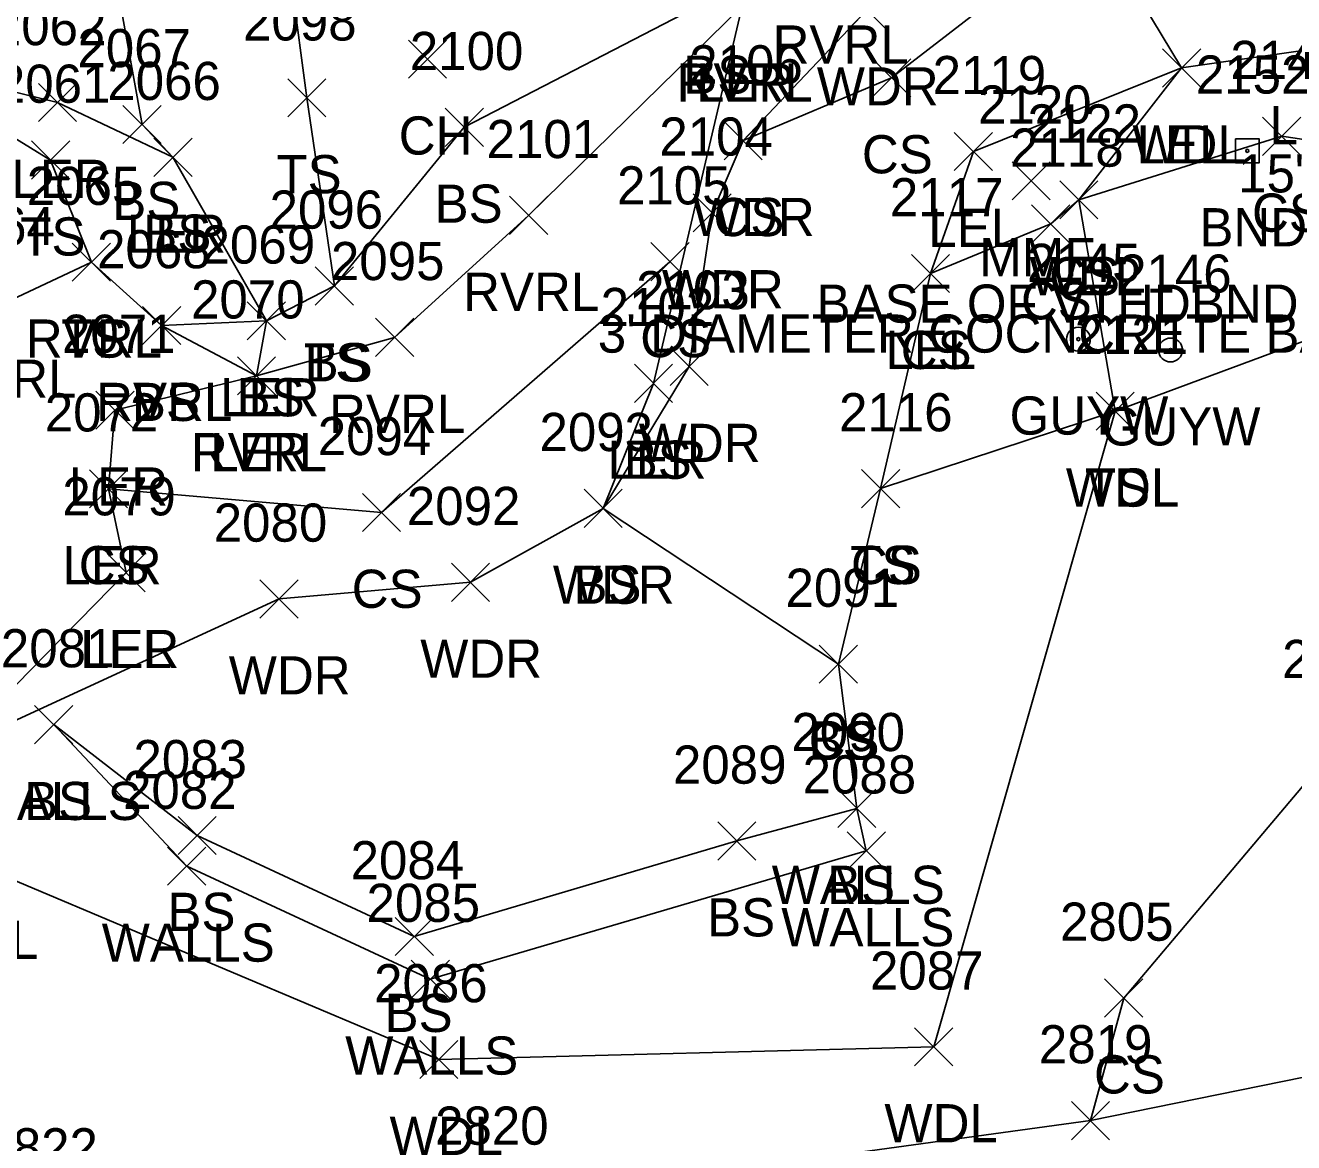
# Model space of a CAD drawing. Extents: x 1504228 to 1506103, y 437717 to 440106.
# Drawn here: x 1505135.1 to 1505201.5, y 438079.5 to 438138 of the extents above; entities that cross this region are included whole.
import ezdxf

# ---------------------------------------------------------------- set-up
doc = ezdxf.new("R2010")
doc.units = 0
for name, color, linetype in [('D_C', 7, 'Continuous'), ('L_A', 7, 'Continuous'), ('L_C', 7, 'Continuous'), ('L_I', 7, 'Continuous'), ('L_TIC', 7, 'Continuous'), ('LARO', 7, 'Continuous'), ('LAWA', 7, 'Continuous'), ('LAWE', 7, 'Continuous'), ('LELB', 7, 'Continuous'), ('LWS', 7, 'Continuous'), ('M_A', 7, 'Continuous'), ('M_C', 7, 'Continuous'), ('M_I', 7, 'Continuous'), ('MHBP', 7, 'Continuous'), ('R_I', 7, 'Continuous'), ('R_TIC', 7, 'Continuous'), ('RDG', 7, 'Continuous'), ('U_A', 7, 'Continuous'), ('U_I', 7, 'Continuous'), ('UPGW', 7, 'Continuous')]:
    doc.layers.add(name, color=color, linetype=linetype)

msp = doc.modelspace()

# ---------------------------------------------------------------- linework, layer by layer
at = {"layer": 'L_TIC'}
for points in [[(1505178.199, 438137.842), (1505180.199, 438139.842)], [(1505180.199, 438137.842), (1505178.199, 438139.842)], [(1505155.163, 438135.267), (1505157.163, 438137.267)], [(1505157.163, 438135.267), (1505155.163, 438137.267)], [(1505194.68, 438134.804), (1505196.68, 438136.804)], [(1505196.68, 438134.804), (1505194.68, 438136.804)], [(1505194.68, 438134.804), (1505196.68, 438136.804)], [(1505196.68, 438134.804), (1505194.68, 438136.804)], [(1505179.482, 438134.284), (1505181.482, 438136.284)], [(1505181.482, 438134.284), (1505179.482, 438136.284)], [(1505148.834, 438133.242), (1505150.834, 438135.242)], [(1505150.834, 438133.242), (1505148.834, 438135.242)], [(1505135.77, 438132.995), (1505137.77, 438134.995)], [(1505137.77, 438132.995), (1505135.77, 438134.995)], [(1505140.2, 438131.842), (1505142.2, 438133.842)], [(1505142.2, 438131.842), (1505140.2, 438133.842)], [(1505157.09, 438131.695), (1505159.09, 438133.695)], [(1505159.09, 438131.695), (1505157.09, 438133.695)], [(1505199.926, 438131.226), (1505201.926, 438133.226)], [(1505201.926, 438131.226), (1505199.926, 438133.226)], [(1505171.704, 438130.996), (1505173.704, 438132.996)], [(1505173.704, 438130.996), (1505171.704, 438132.996)], [(1505171.704, 438130.996), (1505173.704, 438132.996)], [(1505173.704, 438130.996), (1505171.704, 438132.996)], [(1505183.765, 438130.432), (1505185.765, 438132.432)], [(1505185.765, 438130.432), (1505183.765, 438132.432)], [(1505135.412, 438129.979), (1505137.412, 438131.979)], [(1505137.412, 438129.979), (1505135.412, 438131.979)], [(1505141.823, 438130.125), (1505143.823, 438132.125)], [(1505143.823, 438130.125), (1505141.823, 438132.125)], [(1505141.823, 438130.125), (1505143.823, 438132.125)], [(1505143.823, 438130.125), (1505141.823, 438132.125)], [(1505186.794, 438128.891), (1505188.794, 438130.891)], [(1505188.794, 438128.891), (1505186.794, 438130.891)], [(1505189.293, 438127.897), (1505191.293, 438129.897)], [(1505191.293, 438127.897), (1505189.293, 438129.897)], [(1505189.293, 438127.897), (1505191.293, 438129.897)], [(1505191.293, 438127.897), (1505189.293, 438129.897)], [(1505160.461, 438127.08), (1505162.461, 438129.08)], [(1505162.461, 438127.08), (1505160.461, 438129.08)], [(1505170.081, 438127.212), (1505172.081, 438129.212)], [(1505172.081, 438127.212), (1505170.081, 438129.212)], [(1505187.818, 438126.633), (1505189.818, 438128.633)], [(1505189.818, 438126.633), (1505187.818, 438128.633)], [(1505137.547, 438124.629), (1505139.547, 438126.629)], [(1505139.547, 438124.629), (1505137.547, 438126.629)], [(1505137.547, 438124.629), (1505139.547, 438126.629)], [(1505139.547, 438124.629), (1505137.547, 438126.629)], [(1505167.865, 438124.654), (1505169.865, 438126.654)], [(1505169.865, 438124.654), (1505167.865, 438126.654)], [(1505181.517, 438124.035), (1505183.517, 438126.035)], [(1505183.517, 438124.035), (1505181.517, 438126.035)], [(1505181.517, 438124.035), (1505183.517, 438126.035)], [(1505183.517, 438124.035), (1505181.517, 438126.035)], [(1505150.279, 438123.385), (1505152.279, 438125.385)], [(1505152.279, 438123.385), (1505150.279, 438125.385)], [(1505150.279, 438123.385), (1505152.279, 438125.385)], [(1505152.279, 438123.385), (1505150.279, 438125.385)], [(1505141.229, 438121.311), (1505143.229, 438123.311)], [(1505143.229, 438121.311), (1505141.229, 438123.311)], [(1505141.229, 438121.311), (1505143.229, 438123.311)], [(1505143.229, 438121.311), (1505141.229, 438123.311)], [(1505146.715, 438121.555), (1505148.715, 438123.555)], [(1505148.715, 438121.555), (1505146.715, 438123.555)], [(1505146.715, 438121.555), (1505148.715, 438123.555)], [(1505148.715, 438121.555), (1505146.715, 438123.555)], [(1505153.437, 438120.689), (1505155.437, 438122.689)], [(1505155.437, 438120.689), (1505153.437, 438122.689)], [(1505168.869, 438119.164), (1505170.869, 438121.164)], [(1505170.869, 438119.164), (1505168.869, 438121.164)], [(1505146.195, 438118.679), (1505148.195, 438120.679)], [(1505148.195, 438118.679), (1505146.195, 438120.679)], [(1505146.195, 438118.679), (1505148.195, 438120.679)], [(1505148.195, 438118.679), (1505146.195, 438120.679)], [(1505167.002, 438118.282), (1505169.002, 438120.282)], [(1505169.002, 438118.282), (1505167.002, 438120.282)], [(1505167.002, 438118.282), (1505169.002, 438120.282)], [(1505169.002, 438118.282), (1505167.002, 438120.282)], [(1505138.781, 438116.88), (1505140.781, 438118.88)], [(1505140.781, 438116.88), (1505138.781, 438118.88)], [(1505191.198, 438116.824), (1505193.198, 438118.824)], [(1505193.198, 438116.824), (1505191.198, 438118.824)], [(1505191.198, 438116.824), (1505193.198, 438118.824)], [(1505193.198, 438116.824), (1505191.198, 438118.824)], [(1505191.198, 438116.824), (1505193.198, 438118.824)], [(1505193.198, 438116.824), (1505191.198, 438118.824)], [(1505138.442, 438112.761), (1505140.442, 438114.761)], [(1505140.442, 438112.761), (1505138.442, 438114.761)], [(1505138.442, 438112.761), (1505140.442, 438114.761)], [(1505140.442, 438112.761), (1505138.442, 438114.761)], [(1505178.908, 438112.769), (1505180.908, 438114.769)], [(1505180.908, 438112.769), (1505178.908, 438114.769)], [(1505178.908, 438112.769), (1505180.908, 438114.769)], [(1505180.908, 438112.769), (1505178.908, 438114.769)], [(1505152.748, 438111.521), (1505154.748, 438113.521)], [(1505154.748, 438111.521), (1505152.748, 438113.521)], [(1505164.366, 438111.735), (1505166.366, 438113.735)], [(1505166.366, 438111.735), (1505164.366, 438113.735)], [(1505164.366, 438111.735), (1505166.366, 438113.735)], [(1505166.366, 438111.735), (1505164.366, 438113.735)], [(1505139.37, 438108.366), (1505141.37, 438110.366)], [(1505141.37, 438108.366), (1505139.37, 438110.366)], [(1505139.37, 438108.366), (1505141.37, 438110.366)], [(1505141.37, 438108.366), (1505139.37, 438110.366)], [(1505157.417, 438107.861), (1505159.417, 438109.861)], [(1505159.417, 438107.861), (1505157.417, 438109.861)], [(1505147.382, 438106.988), (1505149.382, 438108.988)], [(1505149.382, 438106.988), (1505147.382, 438108.988)], [(1505176.692, 438103.576), (1505178.692, 438105.576)], [(1505178.692, 438103.576), (1505176.692, 438105.576)], [(1505176.692, 438103.576), (1505178.692, 438105.576)], [(1505178.692, 438103.576), (1505176.692, 438105.576)], [(1505135.574, 438100.408), (1505137.574, 438102.408)], [(1505137.574, 438100.408), (1505135.574, 438102.408)], [(1505135.574, 438100.408), (1505137.574, 438102.408)], [(1505137.574, 438100.408), (1505135.574, 438102.408)], [(1505177.656, 438096.017), (1505179.656, 438098.017)], [(1505179.656, 438096.017), (1505177.656, 438098.017)], [(1505177.656, 438096.017), (1505179.656, 438098.017)], [(1505179.656, 438096.017), (1505177.656, 438098.017)], [(1505143.088, 438094.6), (1505145.088, 438096.6)], [(1505145.088, 438094.6), (1505143.088, 438096.6)], [(1505171.369, 438094.311), (1505173.369, 438096.311)], [(1505173.369, 438094.311), (1505171.369, 438096.311)], [(1505178.156, 438093.798), (1505180.156, 438095.798)], [(1505180.156, 438093.798), (1505178.156, 438095.798)], [(1505142.544, 438092.988), (1505144.544, 438094.988)], [(1505144.544, 438092.988), (1505142.544, 438094.988)], [(1505154.469, 438089.305), (1505156.469, 438091.305)], [(1505156.469, 438089.305), (1505154.469, 438091.305)], [(1505155.306, 438087.071), (1505157.306, 438089.071)], [(1505157.306, 438087.071), (1505155.306, 438089.071)], [(1505191.646, 438086.085), (1505193.646, 438088.085)], [(1505193.646, 438086.085), (1505191.646, 438088.085)], [(1505181.688, 438083.526), (1505183.688, 438085.526)], [(1505183.688, 438083.526), (1505181.688, 438085.526)], [(1505155.755, 438082.861), (1505157.755, 438084.861)], [(1505157.755, 438082.861), (1505155.755, 438084.861)], [(1505189.901, 438079.663), (1505191.901, 438081.663)], [(1505191.901, 438079.663), (1505189.901, 438081.663)]]:
    msp.add_lwpolyline(points, dxfattribs=at)
at = {"layer": 'LARO'}
for points in [[(1505168.002, 438119.282), (1505172.649, 438139.038), (1505173.824, 438143.837), (1505173.651, 438150.434), (1505180.265, 438174.662)], [(1505182.517, 438125.035), (1505184.765, 438131.432), (1505195.68, 438135.804), (1505202.648, 438136.805), (1505211.456, 438138.946)], [(1505051.47, 438112.466), (1505065.836, 438109.045), (1505074.957, 438110.498), (1505076.564, 438115.598), (1505086.61, 438112.565), (1505093.048, 438111.253), (1505094.667, 438115.823), (1505099.276, 438121.532), (1505099.736, 438129.007), (1505101.813, 438129.775), (1505110.182, 438128.512), (1505120.189, 438134.563), (1505127.997, 438136.148), (1505136.77, 438133.995), (1505142.823, 438131.125), (1505147.715, 438122.555), (1505147.195, 438119.679), (1505139.781, 438117.88), (1505139.442, 438113.761), (1505140.37, 438109.366)], [(1505105.945, 438101.142), (1505109.593, 438094.033), (1505131.29, 438100.118), (1505140.37, 438109.366)]]:
    msp.add_lwpolyline(points, dxfattribs=at)
at = {"layer": 'LAWA'}
for points in [[(1505045.774, 438104.61), (1505061.758, 438093.168), (1505077.881, 438090.399), (1505093.504, 438098.641), (1505109.795, 438092.212), (1505131.29, 438100.118), (1505148.382, 438107.988), (1505158.417, 438108.861), (1505165.366, 438112.735), (1505169.869, 438120.164), (1505171.081, 438128.212), (1505172.704, 438131.996), (1505179.199, 438138.842), (1505191.063, 438143.467)], [(1505132.404, 438094.128), (1505156.755, 438083.861), (1505182.688, 438084.526), (1505192.198, 438117.824), (1505190.293, 438128.897), (1505195.68, 438135.804), (1505191.063, 438143.467)]]:
    msp.add_lwpolyline(points, dxfattribs=at)
at = {"layer": 'LAWE'}
msp.add_lwpolyline([(1505134.067, 438123.525), (1505138.547, 438125.629), (1505142.229, 438122.311), (1505147.195, 438119.679), (1505154.437, 438121.689), (1505161.461, 438128.08), (1505172.649, 438139.038), (1505177.677, 438141.032), (1505191.715, 438146.002), (1505202.906, 438148.803)], dxfattribs=at)
at = {"layer": 'LELB'}
for points in [[(1505142.229, 438122.311), (1505147.715, 438122.555), (1505151.279, 438124.385), (1505158.09, 438132.695), (1505171.122, 438139.456), (1505173.824, 438143.837), (1505177.453, 438144.004), (1505191.339, 438149.526), (1505195.084, 438151.064), (1505200.044, 438155.753), (1505208.365, 438156.74), (1505216.536, 438157.155)], [(1505141.2, 438132.842), (1505137.265, 438154.64)], [(1505172.704, 438131.996), (1505180.482, 438135.284), (1505191.063, 438143.467), (1505202.746, 438145.507), (1505208.637, 438147.002), (1505213.787, 438148.55)], [(1505151.279, 438124.385), (1505149.834, 438134.242), (1505148.272, 438146.065)], [(1505127.997, 438136.148), (1505136.412, 438130.979), (1505138.547, 438125.629)], [(1505177.692, 438104.576), (1505179.908, 438113.769), (1505182.517, 438125.035), (1505188.818, 438127.633), (1505190.293, 438128.897), (1505200.926, 438132.226), (1505206.927, 438131.324), (1505213.65, 438134.809)], [(1505142.823, 438131.125), (1505141.2, 438132.842)], [(1505192.198, 438117.824), (1505205.477, 438122.757), (1505214.761, 438127.389)], [(1505139.442, 438113.761), (1505153.748, 438112.521), (1505168.865, 438125.654)], [(1505136.574, 438101.408), (1505144.088, 438095.6), (1505155.469, 438090.305), (1505172.369, 438095.311), (1505178.656, 438097.017), (1505177.692, 438104.576), (1505165.366, 438112.735), (1505168.002, 438119.282)], [(1505179.908, 438113.769), (1505192.198, 438117.824)], [(1505214.625, 438113.719), (1505204.287, 438100.846), (1505192.646, 438087.085), (1505190.901, 438080.663)]]:
    msp.add_lwpolyline(points, dxfattribs=at)
at = {"layer": 'LWS'}
msp.add_lwpolyline([(1505136.574, 438101.408), (1505143.544, 438093.988), (1505156.306, 438088.071), (1505179.156, 438094.798), (1505178.656, 438097.017)], dxfattribs=at)
at = {"layer": 'MHBP'}
msp.add_lwpolyline([(1505198.495, 438132.086), (1505199.745, 438132.086), (1505199.745, 438130.836), (1505198.495, 438130.836)], close=True, dxfattribs=at)
msp.add_circle((1505199.12, 438131.461), 0.0833, dxfattribs=at)
at = {"layer": 'R_TIC'}
for points in [[(1505189.901, 438079.663), (1505191.901, 438081.663)], [(1505191.901, 438079.663), (1505189.901, 438081.663)]]:
    msp.add_lwpolyline(points, dxfattribs=at)
at = {"layer": 'RDG'}
msp.add_lwpolyline([(1505226.014, 438093.521), (1505215.58, 438085.68), (1505190.901, 438080.663), (1505159.904, 438076.4), (1505136.198, 438075.264)], dxfattribs=at)
at = {"layer": 'UPGW'}
for centre, radius in [((1505190.269, 438121.597), 0.625), ((1505190.269, 438121.597), 0.0833), ((1505195.097, 438121.03), 0.625), ((1505195.097, 438121.03), 0.0833)]:
    msp.add_circle(centre, radius, dxfattribs=at)

# ---------------------------------------------------------------- texts
at = {"layer": 'D_C'}
msp.add_text('15"CGMP', height=2, dxfattribs=at).set_placement((1505198.645, 438129.283))
at = {"layer": 'L_A'}
for s, p in [('RVRL', (1505174.244, 438136.032)), ('BS', (1505169.563, 438134.456)), ('RVRL', (1505169.216, 438134.038)), ('LER', (1505170.232, 438134.038)), ('WDR', (1505176.562, 438133.842)), ('LEL', (1505200.286, 438131.805)), ('CH', (1505154.652, 438131.267)), ('WDL', (1505193.097, 438130.804)), ('LEL', (1505193.318, 438130.804)), ('CS', (1505178.923, 438130.284)), ('TS', (1505148.243, 438129.242)), ('LER', (1505134.353, 438128.995)), ('BS', (1505139.641, 438127.842)), ('BS', (1505156.531, 438127.695)), ('CS', (1505199.366, 438127.226)), ('WDR', (1505170.066, 438126.996)), ('CS', (1505171.145, 438126.996)), ('LEL', (1505182.403, 438126.432)), ('TS', (1505134.821, 438125.979)), ('LER', (1505140.405, 438126.125)), ('BS', (1505141.264, 438126.125)), ('MMF', (1505185.077, 438124.891)), ('WDL', (1505187.71, 438123.897)), ('CS', (1505188.734, 438123.897)), ('RVRL', (1505158.028, 438123.08)), ('WDR', (1505168.443, 438123.212)), ('CS', (1505187.259, 438122.633)), ('RVRL', (1505135.114, 438120.629)), ('TS', (1505136.956, 438120.629)), ('CS', (1505167.306, 438120.654)), ('LEL', (1505180.155, 438120.035)), ('CS', (1505180.958, 438120.035)), ('TS', (1505149.689, 438119.385)), ('BS', (1505149.72, 438119.385)), ('RVRL', (1505130.634, 438118.525)), ('RVRL', (1505138.796, 438117.311)), ('BS', (1505140.67, 438117.311)), ('LER', (1505145.298, 438117.555)), ('BS', (1505146.156, 438117.555)), ('RVRL', (1505151.004, 438116.689)), ('WDR', (1505167.231, 438115.164)), ('RVRL', (1505143.762, 438114.679)), ('LER', (1505144.778, 438114.679)), ('LER', (1505165.585, 438114.282)), ('BS', (1505166.443, 438114.282)), ('LER', (1505137.364, 438112.88)), ('WDL', (1505189.615, 438112.824)), ('TS', (1505190.608, 438112.824)), ('TS', (1505190.608, 438112.824)), ('LER', (1505137.025, 438108.761)), ('CS', (1505137.883, 438108.761)), ('TS', (1505178.318, 438108.769)), ('CS', (1505178.349, 438108.769)), ('CS', (1505152.189, 438107.521)), ('WDR', (1505162.729, 438107.735)), ('BS', (1505163.807, 438107.735)), ('LER', (1505137.952, 438104.366)), ('LEL', (1505138.008, 438104.366)), ('WDR', (1505155.779, 438103.861)), ('WDR', (1505145.744, 438102.988)), ('CS', (1505176.133, 438099.576)), ('BS', (1505176.133, 438099.576)), ('WALLS', (1505132.118, 438096.408)), ('BS', (1505135.015, 438096.408)), ('WALLS', (1505174.199, 438092.017)), ('BS', (1505177.097, 438092.017)), ('BS', (1505142.529, 438090.6)), ('BS', (1505170.81, 438090.311)), ('WALLS', (1505174.7, 438089.798)), ('WDL', (1505129.821, 438089.128)), ('WALLS', (1505139.087, 438088.988)), ('BS', (1505153.91, 438085.305)), ('WALLS', (1505151.849, 438083.071)), ('CS', (1505191.087, 438082.085)), ('WDL', (1505180.105, 438079.526)), ('WDL', (1505154.173, 438078.861))]:
    msp.add_text(s, height=2, dxfattribs=at).set_placement(p)
at = {"layer": 'L_C'}
msp.add_text("3' DIAMETER COCNCRETE BASE", height=2, dxfattribs=at).set_placement((1505165.085, 438120.891))
at = {"layer": 'L_I'}
for s, p in [('2062', (1505133.384, 438136.995)), ('2098', (1505146.495, 438137.242)), ('2067', (1505137.815, 438135.842)), ('2100', (1505155.232, 438135.695)), ('2143', (1505198.233, 438135.226)), ('2106', (1505169.877, 438134.996)), ('2106', (1505169.877, 438134.996)), ('2119', (1505182.631, 438134.432)), ('2061', (1505133.593, 438133.979)), ('2066', (1505139.382, 438134.125)), ('2066', (1505139.382, 438134.125)), ('2120', (1505185.014, 438132.891)), ('2122', (1505187.6, 438131.897)), ('2122', (1505187.6, 438131.897)), ('2101', (1505159.257, 438131.08)), ('2104', (1505168.309, 438131.212)), ('2118', (1505186.692, 438130.633)), ('2065', (1505135.161, 438128.629)), ('2065', (1505135.161, 438128.629)), ('2105', (1505166.093, 438128.654)), ('2117', (1505180.391, 438128.035)), ('2117', (1505180.391, 438128.035)), ('2096', (1505147.885, 438127.385)), ('2096', (1505147.885, 438127.385)), ('2064', (1505130.681, 438126.525)), ('2068', (1505138.844, 438125.311)), ('2068', (1505138.844, 438125.311)), ('2069', (1505144.322, 438125.555)), ('2069', (1505144.322, 438125.555)), ('2095', (1505151.099, 438124.689)), ('2103', (1505167.097, 438123.164)), ('2070', (1505143.77, 438122.679)), ('2070', (1505143.77, 438122.679)), ('2102', (1505165.231, 438122.282)), ('2102', (1505165.231, 438122.282)), ('2071', (1505137.009, 438120.88)), ('2121', (1505190.072, 438120.824)), ('2121', (1505190.072, 438120.824)), ('2121', (1505190.072, 438120.824)), ('2072', (1505136.104, 438116.761)), ('2072', (1505136.104, 438116.761)), ('2116', (1505177.727, 438116.769)), ('2116', (1505177.727, 438116.769)), ('2093', (1505162.028, 438115.735)), ('2093', (1505162.028, 438115.735)), ('2094', (1505150.41, 438115.521)), ('2079', (1505137.023, 438112.366)), ('2079', (1505137.023, 438112.366)), ('2092', (1505155.078, 438111.861)), ('2080', (1505144.957, 438110.988)), ('2091', (1505174.921, 438107.576)), ('2091', (1505174.921, 438107.576)), ('2081', (1505133.803, 438104.408)), ('2081', (1505133.803, 438104.408)), ('2804', (1505200.948, 438103.846)), ('2090', (1505175.23, 438100.017)), ('2090', (1505175.23, 438100.017)), ('2083', (1505140.75, 438098.6)), ('2089', (1505169.023, 438098.311)), ('2088', (1505175.818, 438097.798)), ('2082', (1505140.206, 438096.988)), ('2084', (1505152.131, 438093.305)), ('2085', (1505152.967, 438091.071)), ('2805', (1505189.307, 438090.085)), ('2087', (1505179.349, 438087.526)), ('2086', (1505153.362, 438086.861)), ('2819', (1505188.2, 438083.663)), ('2822', (1505132.938, 438078.264))]:
    msp.add_text(s, height=2, dxfattribs=at).set_placement(p)
at = {"layer": 'M_A'}
msp.add_text('BND', height=2, dxfattribs=at).set_placement((1505196.609, 438126.461))
at = {"layer": 'M_C'}
msp.add_text('BASE OF VTHDBND DISTURBED', height=2, dxfattribs=at).set_placement((1505176.546, 438122.461))
at = {"layer": 'M_I'}
msp.add_text('2152', height=2, dxfattribs=at).set_placement((1505196.427, 438134.461))
at = {"layer": 'R_I'}
for s, p in [('2819', (1505188.2, 438083.663)), ('2820', (1505156.557, 438079.4)), ('2822', (1505132.938, 438078.264))]:
    msp.add_text(s, height=2, dxfattribs=at).set_placement(p)
at = {"layer": 'U_A'}
for p in [(1505186.663, 438116.597), (1505191.491, 438116.03)]:
    msp.add_text('GUYW', height=2, dxfattribs=at).set_placement(p)
at = {"layer": 'U_I'}
for s, p in [('2145', (1505187.577, 438124.597)), ('2146', (1505192.349, 438124.03))]:
    msp.add_text(s, height=2, dxfattribs=at).set_placement(p)

doc.saveas('drawing.dxf')
